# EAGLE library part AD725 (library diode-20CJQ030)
Analog Devices AD725 Low Cost RGB to NTSC/PAL Encoder with Luma Trap Port Description: The AD725 is a very low cost general purpose RGB to NTSC/ PAL encoder that converts red, green and blue color component signals into their corresponding luminance (baseband amplitude) and chrominance (subcarrier amplitude and phase) signals in accordance with either NTSC or PAL standards. These two outputs are also combined on-chip to provide a composite video output. All three outputs are available separately at voltages of twice the standard signal levels as required for driving 75 Ohm, reverse-terminated cables. The AD725 features a luminance trap (YTRAP) pin that provides a means of reducing cross color generated by subcarrier frequency components found in the luminance signal. For portable or other power-sensitive applications, the device can be powered down to less than 1 uA of current consumption. All logic levels are TTL compatible thus supporting the logic requirements of 3 V CMOS systems. The AD725 is packaged in a low cost 16-lead SOIC and operates from a +5 V supply. Features: Composite Video Output: Both NTSC and PAL Chrominance and Luminance (S-Video) Outputs Luma Trap Port to Eliminate Cross Color Artifacts TTL Logic Levels Integrated Delay Line and Auto-Tuned Filters Drives 75 Ohm Reverse-Terminated Loads Low Power +5 V Operation Power-Down to less then 1 uA Very Low Cost Applications: RGB/VGA to NTSC/PAL Encoding Personal Computers/Network Computers Video Games Video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
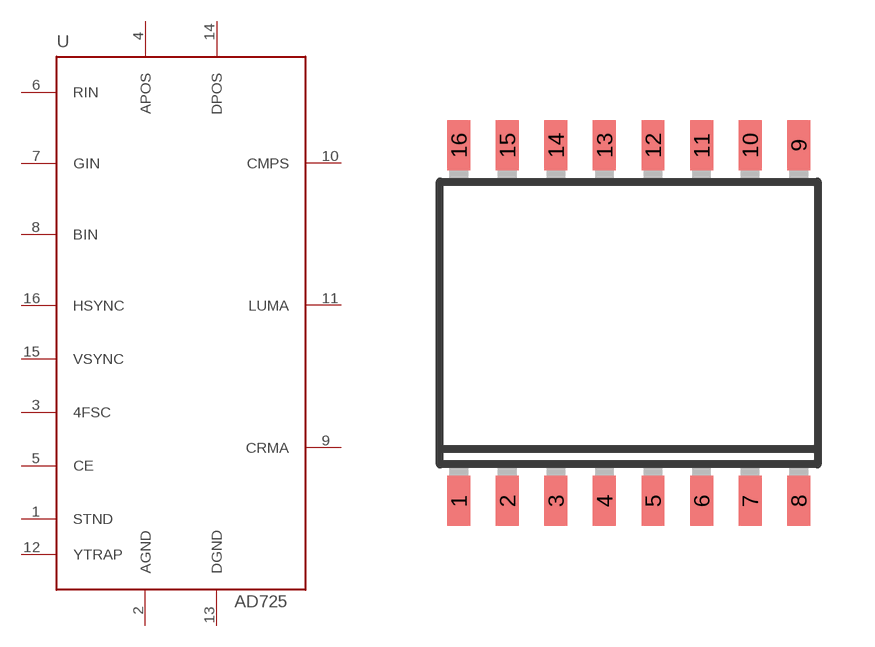
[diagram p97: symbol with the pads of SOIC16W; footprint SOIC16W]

Designator prefix U

## AD725  [SOIC16W]
1  STND  in
2  AGND  pwr
3  4FSC  in
4  APOS  pwr
5  CE  in
6  RIN  in
7  GIN  in
8  BIN  in
9  CRMA  out
10  CMPS  out
11  LUMA  out
12  YTRAP  out
13  DGND  pwr
14  DPOS  pwr
15  VSYNC  in
16  HSYNC  in

## Footprint SOIC16W (pad centres in mm)
Small Outline Package wide source www.motorola.com; BR1568.pdf
smd 0.6 x 1.3: 1 -4.445,-4.65; 2 -3.175,-4.65; 3 -1.905,-4.65; 4 -0.635,-4.65; 5 0.635,-4.65; 6 1.905,-4.65; 7 3.175,-4.65; 8 4.445,-4.65; 9 4.445,4.65; 10 3.175,4.65; 11 1.905,4.65; 12 0.635,4.65; 13 -0.635,4.65; 14 -1.905,4.65; 15 -3.175,4.65; 16 -4.445,4.65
